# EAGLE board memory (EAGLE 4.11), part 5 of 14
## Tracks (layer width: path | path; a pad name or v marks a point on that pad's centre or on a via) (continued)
-MB08  (via drill 0.61) (continued)
  Bottom 0.254: F11.R2 370.2,26.03 374.65,26.03 375.92,27.3 378.46,27.3 379.1,26.67 387.99,26.67 391.8,30.48 394.33,30.48 397.51,27.3 403.86,27.3 404.5,26.67 413.38,26.67 414.02,27.3 416.56,27.3 417.19,26.67 421.64,26.67 423.55,24.77 423.55,22.86 F07.S2 | v11.43,186.06 13.97,186.06 13.97,181.61 D39.J2 | v13.34,201.29 26.04,214 67.31,214 68.58,212.72 74.93,212.72 75.56,213.36 130.18,213.36 131.44,212.09 134.62,215.26 147.96,215.26 149.22,216.53 160.02,216.53 160.66,215.9 161.93,215.9 v163.19,217.17 | v165.1,240.66 165.74,240.03 171.45,240.03 v172.72,241.3 | v175.9,244.47 176.53,243.84 177.8,243.84 178.44,243.2 182.25,243.2 185.42,246.38 187.96,246.38 188.59,245.75 197.49,245.75 198.12,246.38 200.66,246.38 201.29,245.75 206.38,245.75 207.65,247.01 C24.K2 208.28,248.28 212.09,248.28 213.36,249.56 218.44,249.56 221.62,252.73 224.16,252.73 224.79,252.09 231.14,252.09 v231.78,251.46 | v287.65,283.85 286.38,282.58 269.24,282.58 v268.61,283.21 | v267.97,274.96 255.91,274.96 255.27,274.32 253.37,274.32 250.82,276.86 237.49,276.86 235.59,274.96 v233.04,274.96 | v19.05,412.75 135.89,412.75 137.79,414.66 v144.15,414.66 | v147.96,410.85 149.22,412.12 155.57,412.12 156.84,413.39 189.23,413.39 190.5,412.12 196.22,412.12 198.12,414.02 249.56,414.02 250.82,412.75 267.33,412.75 267.97,412.12 285.12,412.12 v285.75,411.48 | v276.23,365.76 276.23,363.22 286.38,363.22 287.02,363.86 288.29,363.86 289.56,362.59 292.1,362.59 292.74,363.22 294.64,363.22 v295.27,362.59 | v361.95,27.94 360.68,26.67 351.79,26.67 351.15,27.3 342.26,27.3 341.63,26.67 339.09,26.67 338.45,27.3 329.56,27.3 328.93,26.67 326.39,26.67 320.04,33.02 314.96,33.02 313.69,34.29 311.15,34.29 310.51,33.66 306.7,33.66 v303.53,36.83
  Bottom 0.254: v291.46,50.8 290.83,50.16 288.93,50.16 287.65,48.9 278.76,48.9 278.13,49.53 275.59,49.53 274.95,48.9 266.06,48.9 265.43,49.53 262.89,49.53 262.25,48.9 253.37,48.9 252.73,49.53 250.19,49.53 249.56,48.9 247.01,48.9 v242.57,53.34 | v239.4,81.28 238.76,80.64 185.42,80.64 v179.71,86.36 | v180.97,200.66 180.34,201.29 173.99,201.29 173.35,201.93 v167,201.93
-MB09  (via drill 0.61)
  Top 0.254: v15.88,13.97 15.88,42.55 14.61,43.82 F39.J2 | v260.35,5.08 275.59,5.08 276.86,3.81 278.13,3.81 v278.13,11.43 | v204.47,201.93 204.47,212.72 206.38,214.63 206.38,239.39 207.65,240.66 C24.M2 | v165.1,168.28 165.1,156.21 156.84,147.95 156.84,139.06 155.57,137.79 155.57,16.51 147.32,8.25 147.32,4.44 146.05,3.17 144.15,3.17 v142.24,5.08
  Route2 0.254: v142.24,5.08 144.78,2.54 220.34,2.54 222.25,0.63 255.91,0.63 v260.35,5.08 | v278.13,11.43 280.04,9.52 316.23,9.52 317.5,8.25 341.63,8.25 343.54,10.16 352.43,10.16 359.41,17.14 363.86,17.14 365.12,18.41 369.57,18.41 F11.T2 | v204.47,201.93 203.84,201.29 200.03,201.29 196.85,204.47 192.41,204.47 189.23,201.29 186.69,201.29 186.06,201.93 179.71,201.93 176.53,205.1 175.9,205.1 174.62,203.84 173.99,203.84 173.35,204.47 168.28,204.47 v163.83,200.03
  Route3 0.254: v163.83,200.03 161.93,198.12 161.93,191.13 160.66,189.86 165.1,185.42 v165.1,168.28
  Bottom 0.254: v15.88,13.97 23.5,6.35 137.16,6.35 138.43,5.08 v142.24,5.08
-MB10  (via drill 0.61)
  Top 0.254: v28.57,9.52 28.57,38.73 27.94,39.37 27.94,43.18 27.3,43.82 F38.J2 | v226.69,9.52 v226.69,4.44 | v344.81,6.35 346.07,7.62 346.07,29.84 347.35,31.12 347.35,33.02 344.81,35.56 344.81,37.46 F13.L2 | v201.29,231.78 200.03,230.5 200.03,211.45 198.12,209.55 v198.12,201.93 | v191.13,201.29 190.5,200.66 190.5,175.89 v189.23,174.62 | v182.25,82.55 180.34,80.64 180.34,64.77 180.97,64.13 180.97,17.78 177.8,14.61 177.8,8.89 v179.07,7.62
  Route2 0.254: v345.44,85.72 346.71,86.99 351.15,86.99 354.96,90.8 363.86,90.8 364.49,90.17 373.38,90.17 382.9,99.69 389.25,99.69 389.89,100.33 400.05,100.33 400.05,120.02 395.61,124.46 395.61,126.36 E09.D2 | v201.29,231.78 202.56,231.78 203.84,233.04 206.38,233.04 207.65,234.31 C24.P2 | v198.12,201.93 197.49,201.29 v191.13,201.29
  Route3 0.254: v345.44,85.72 346.71,84.45 346.71,69.85 349.25,67.31 349.25,52.7 342.9,46.36 342.9,40.01 344.17,38.73 F13.L2 | v189.23,174.62 188.59,173.99 188.59,173.35 184.15,168.91 184.15,84.45 v182.25,82.55
  Bottom 0.254: v28.57,9.52 29.84,8.25 135.25,8.25 136.53,9.52 138.43,9.52 139.7,8.25 179.07,8.25 | 179.07,8.25 219.07,8.25 220.34,9.52 v226.69,9.52 | v226.69,4.44 227.33,3.81 274.32,3.81 277.5,6.98 302.89,6.98 304.8,5.08 314.96,5.08 316.23,6.35 342.26,6.35 342.9,6.98 344.17,6.98 v344.81,6.35 | v179.07,7.62 179.07,8.25
-MB11  (via drill 0.61)
  Top 0.254: v349.25,51.44 349.25,70.48 350.52,71.75 v350.52,78.1 | v426.72,78.74 431.8,78.74 431.8,106.04 433.07,107.31 E06.L2 | v38.1,69.85 38.1,46.36 39.37,45.09 F37.J2 | v146.05,140.97 v146.05,71.75 | v248.92,140.97 250.82,142.88 250.82,151.76 | 250.82,151.76 v250.82,170.18 | v214,225.42 215.9,223.52 v215.9,208.91 | v238.12,207.64 240.66,207.64 240.66,204.47 241.3,203.84 241.3,186.06 v242.57,184.78 | v322.58,95.25 321.31,96.52 321.31,97.16 320.68,97.79 v320.68,100.96 | v253.37,113.03 254,113.66 254,119.38 252.73,120.65 252.73,121.92 254,123.19 254,139.7 252.73,140.97 252.73,147.95 253.37,148.59 253.37,149.22 250.82,151.76
  Route2 0.254: v349.25,51.44 344.81,51.44 F13.F2
  Route3 0.254: v350.52,78.1 350.52,80.64 349.25,81.91 349.25,86.99 v341,95.25
  Bottom 0.254: v350.52,78.1 365.76,78.1 367.67,80.01 407.04,80.01 408.31,78.74 v426.72,78.74 | E06.E2 436.88,123.19 436.88,118.74 437.51,118.74 444.5,111.76 444.5,109.22 440.69,109.22 440.06,109.85 438.15,109.85 436.25,107.95 433.7,107.95 E06.L2 | v38.1,69.85 40.01,71.75 v146.05,71.75 | v146.05,140.97 146.69,140.34 248.28,140.34 v248.92,140.97 | 250.82,172.72 250.82,174.62 255.27,174.62 D20.L2 | v250.82,170.18 250.82,172.72 | v214,225.42 212.09,227.33 208.91,227.33 208.28,227.97 C24.S2 | v215.9,208.91 217.17,207.64 229.24,207.64 229.87,207.01 237.49,207.01 v238.12,207.64 | v242.57,184.78 240.03,182.25 237.49,182.25 236.85,182.88 236.22,182.88 231.78,178.44 231.78,176.53 234.95,176.53 235.59,177.16 238.12,177.16 239.4,175.89 245.75,175.89 248.92,172.72 250.82,172.72 | v341,95.25 339.09,93.34 329.56,93.34 328.93,93.98 326.39,93.98 325.75,93.34 324.49,93.34 v322.58,95.25 | v320.68,100.96 320.68,102.87 314.96,102.87 311.15,106.68 300.99,106.68 300.36,106.04 291.46,106.04 287.65,109.85 285.12,109.85 281.94,106.68 278.13,106.68 274.95,109.85 266.06,109.85 265.43,109.22 262.89,109.22 262.25,109.85 256.54,109.85 v253.37,113.03
-MBSH  (via drill 0.61)
  Top 0.254: D16.U2 309.25,153.03 307.98,154.31 307.98,165.73 306.7,167 306.7,167.64 D16.N2 | F05.K2 448.94,41.91 447.68,43.18 447.68,55.25 446.4,56.52 F05.D2 | v433.7,116.2 431.8,118.11 431.8,125.09 433.07,126.36 E06.D2 433.07,127.63 431.8,128.91 431.8,142.24 v429.89,144.14 | 371.48,170.18 370.2,168.91 D11.N2 | 371.48,175.89 371.48,170.18 | 371.48,175.89 372.75,177.16 D11.K2 | 371.48,170.18 371.48,154.31 372.75,153.03 D11.U2 373.38,151.76 v373.38,143.51 | 371.48,175.89 371.48,191.77 370.2,193.04 D11.D2 | v443.23,57.15 441.32,59.05 441.32,109.22 v439.42,111.12
  Route2 0.254: v443.23,57.15 445.77,57.15 F05.D2
  Bottom 0.254: D16.N2 306.7,168.91 307.98,170.18 314.96,170.18 316.23,168.91 318.77,168.91 D15.N2 319.4,168.91 320.68,170.18 325.75,170.18 327.02,168.91 331.47,168.91 D14.N2 332.11,168.91 334.01,168.91 335.28,170.18 338.45,170.18 339.73,168.91 344.17,168.91 D13.N2 344.81,167.64 346.07,166.37 353.06,166.37 354.33,167.64 356.87,167.64 D12.N2 357.5,168.91 358.77,170.18 365.76,170.18 367.03,168.91 369.57,168.91 D11.N2 | D16.U2 309.88,151.76 312.42,151.76 313.69,150.5 320.68,150.5 321.94,151.76 D15.U2 322.58,153.03 326.39,153.03 327.66,154.31 328.93,154.31 330.2,153.03 334.64,153.03 D14.U2 335.28,153.03 339.73,153.03 341,154.31 341.63,154.31 342.26,153.67 346.71,153.67 347.35,153.03 D13.U2 347.98,153.03 350.52,153.03 351.79,154.31 354.33,154.31 356.24,152.4 360.05,152.4 D12.U2 | D16.D2 306.7,194.31 307.98,195.58 313.69,195.58 315.6,193.67 318.77,193.67 D15.D2 319.4,194.31 320.68,195.58 326.39,195.58 328.3,193.67 331.47,193.67 D14.D2 332.11,194.31 333.38,195.58 339.09,195.58 341,193.67 344.17,193.67 D13.D2 344.81,194.31 346.07,195.58 351.79,195.58 353.69,193.67 356.87,193.67 D12.D2 357.5,194.31 358.77,195.58 364.49,195.58 366.39,193.67 369.57,193.67 D11.D2 | D16.K2 309.88,178.44 314.32,178.44 315.6,179.7 316.87,179.7 318.13,178.44 321.94,178.44 D15.K2 322.58,178.44 327.02,178.44 328.3,179.7 329.56,179.7 330.83,178.44 334.64,178.44 D14.K2 335.28,178.44 339.73,178.44 341,179.7 346.07,179.7 347.35,178.44 D13.K2 347.98,177.8 351.79,177.8 353.69,179.7 354.96,179.7 356.24,178.44 360.05,178.44 D12.K2 360.68,177.8 364.49,177.8 366.39,175.89 371.48,175.89 372.75,177.16 D11.K2 373.38,177.16 375.92,177.16 377.19,175.89 385.44,175.89 385.44,172.09 D10.M2
  Bottom 0.254: v433.7,116.2 436.25,116.2 436.25,111.76 E06.K2 436.88,111.12 v439.42,111.12 | v429.89,144.14 412.75,144.14 412.12,143.51 398.14,143.51 396.88,142.24 382.27,142.24 381,143.51 v373.38,143.51
-MCA  (via drill 0.61)
  Top 0.254: v80.01,147.95 79.38,148.59 v79.38,214.63 | v131.44,213.36 132.08,214 132.08,220.34 133.35,221.61 133.35,233.04 135.25,234.95 v135.25,235.59 | C29.H2 144.78,253.36 144.78,249.56 146.05,248.28 146.05,236.85 144.78,235.59 C29.P2
  Route3 0.254: v14.61,152.4 14.61,154.94 D39.T2
  Bottom 0.254: v14.61,152.4 19.68,147.32 35.56,147.32 39.37,151.13 48.26,151.13 48.9,150.5 55.24,150.5 58.42,147.32 77.47,147.32 78.11,147.95 v80.01,147.95 | v79.38,214.63 80.01,214 130.81,214 v131.44,213.36 | v135.25,235.59 136.53,236.85 142.88,236.85 144.15,235.59 C29.P2
-MCB  (via drill 0.61)
  Top 0.254: v139.7,228.6 139.7,250.19 132.08,257.81 132.08,259.72 C30.E2
  Route2 0.254: v139.7,228.6 144.15,228.6 C29.S2
-MCC
  Top 0.254: C30.P2 132.08,235.59 132.72,236.22 132.72,240.03 133.35,240.66 133.35,252.09 132.08,253.36 C30.H2
-MCD  (via drill 0.61)
  Top 0.254: v128.91,259.08 136.53,251.46 136.53,243.84 135.25,242.57 135.25,241.3 133.35,239.39 133.35,234.31 132.72,233.68 132.72,229.87 132.08,229.23 C30.S2
  Bottom 0.254: v128.91,259.08 128.27,258.44 124.46,258.44 123.19,259.72 119.38,259.72 C31.E2
-MCE
  Top 0.254: C31.P2 119.38,235.59 119.38,239.39 120.65,240.66 120.65,252.09 119.38,253.36 C31.H2
-MCF  (via drill 0.61)
  Top 0.254: 107.95,227.33 107.95,254.63 106.68,255.91 106.68,259.72 C32.E2 | 107.95,227.33 107.95,196.22 107.31,195.58 107.31,191.77 106.68,191.13 D32.E2 | 107.95,227.33 v109.86,227.33
  Bottom 0.254: v109.86,227.33 110.49,226.69 117.47,226.69 118.75,227.97 C31.S2
-MCG
  Route3 0.254: C32.P2 106.05,235.59 104.78,236.85 104.78,248.92 106.05,250.19 106.05,253.36 C32.H2
-MCH  (via drill 0.61)
  Top 0.254: v24.13,155.57 24.77,156.21 24.77,157.48 25.4,158.11 v25.4,206.38 | v98.42,207.64 98.42,222.88 v99.69,224.16 | v114.3,229.87 v114.3,261.62
  Bottom 0.254: v24.13,155.57 22.23,153.67 18.41,153.67 17.78,153.03 D39.U2 | v25.4,206.38 26.67,207.64 31.75,207.64 32.38,207.01 68.58,207.01 69.85,208.28 73.03,208.28 74.3,207.01 97.79,207.01 v98.42,207.64 | v99.69,224.16 103.5,227.97 106.05,227.97 C32.S2 106.68,229.23 111.12,229.23 112.39,230.5 113.67,230.5 v114.3,229.87 | v114.3,261.62 122.56,261.62 123.19,262.25 125.73,262.25 126.36,261.62 135.25,261.62 135.89,262.25 142.88,262.25 144.15,260.99 C29.E2
-MEM00  (via drill 0.61)
  Top 0.254: v142.24,45.72 146.05,45.72 146.05,70.48 v147.32,71.75 | F22.D2 230.5,57.79 230.5,58.42 231.78,59.69 v231.78,72.39 230.5,73.66 230.5,80.01 228.6,81.91 228.6,90.17 v229.87,91.44 | 238.76,238.12 238.12,238.76 v238.12,253.36 | 238.76,238.12 v240.03,236.85 | v236.22,234.95 238.76,237.49 238.76,238.12
  Route2 0.254: v367.03,217.81 364.49,217.81 363.22,216.53 317.5,216.53 309.88,224.16 304.17,224.16 v297.18,231.14 | v238.12,253.36 233.04,258.44 226.69,258.44 222.25,262.89 217.81,262.89 C23.D2
  Route3 0.254: v367.03,217.81 368.3,216.53 368.3,189.23 369.57,187.96 D11.F2 | v240.03,101.6 238.12,103.5 238.12,116.84 234.95,120.02 234.95,132.08 v233.04,133.99 | v230.5,135.25 227.97,137.79 227.97,151.13 228.6,151.76 228.6,211.45 234.31,217.17 234.31,220.98 234.95,221.61 234.95,233.68 v236.22,234.95
  Bottom 0.254: v142.24,45.72 137.79,45.72 137.16,46.36 132.08,46.36 132.08,41.91 F30.K2 | v147.32,71.75 147.96,72.39 189.87,72.39 190.5,71.75 191.77,71.75 192.41,72.39 210.19,72.39 210.82,73.02 231.14,73.02 v231.78,72.39 | v297.18,231.14 295.27,233.04 288.29,233.04 287.65,233.68 278.76,233.68 278.13,233.04 275.59,233.04 274.95,233.68 268.61,233.68 267.97,233.04 262.89,233.04 262.25,233.68 253.37,233.68 252.73,233.04 252.09,233.04 248.28,236.85 v240.03,236.85 | v229.87,91.44 v240.03,101.6 | v233.04,133.99 231.78,135.25 v230.5,135.25
-MEM01  (via drill 0.61)
  Top 0.254: v130.18,43.18 130.18,36.83 131.44,35.56 F30.M2
  Route2 0.254: D11.R2 370.2,161.29 370.2,159.38 371.48,158.11 371.48,145.41 361.95,145.41 357.5,140.97 321.94,140.97 320.68,142.24 299.72,142.24 298.45,140.97 255.27,140.97 252.73,138.43 251.46,138.43 v249.56,136.53 248.28,135.25 243.21,135.25 238.12,140.34 221.62,140.34 v217.81,144.14
  Route3 0.254: v249.56,136.53 247.65,134.62 247.65,81.91 250.82,78.74 250.82,66.04 255.27,61.59 v255.27,59.05 | v217.81,144.14 212.72,149.22 212.72,200.66 211.46,201.93 211.46,213.36 212.72,214.63 212.72,256.54 217.17,256.54 C23.F2
  Bottom 0.254: v130.18,43.18 130.18,48.9 137.16,48.9 137.79,49.53 139.06,49.53 139.7,48.9 149.86,48.9 150.5,49.53 159.38,49.53 160.02,48.9 162.56,48.9 163.19,49.53 172.09,49.53 172.72,48.9 175.26,48.9 175.9,49.53 184.78,49.53 185.42,48.9 187.96,48.9 188.59,49.53 197.49,49.53 198.12,48.9 200.66,48.9 201.29,49.53 207.65,49.53 210.82,52.7 213.36,52.7 214,52.07 222.88,52.07 226.69,55.88 231.78,55.88 233.04,54.61 F22.E2 233.68,54.61 236.22,54.61 237.49,55.88 240.03,55.88 240.66,55.25 251.46,55.25 v255.27,59.05
-MEM02  (via drill 0.61)
  Top 0.254: v136.53,8.25 136.53,27.94 132.08,27.94 F30.P2 | v229.24,10.79 228.6,11.43 228.6,48.9 229.87,50.16 F22.F2 | v356.87,207.64 358.77,205.74 358.77,189.23 357.5,187.96 D12.F2 | v338.45,212.72 v338.45,207.64 | v242.57,208.91 239.4,212.09 v239.4,219.07 | v229.24,224.16 228.6,224.79 228.6,243.2 v224.16,247.65
  Route2 0.254: v356.87,207.64 355.6,208.91 349.88,208.91 347.98,207.01 339.09,207.01 v338.45,207.64 | v338.45,212.72 336.55,210.82 277.5,210.82 272.42,205.74 245.75,205.74 v242.57,208.91 | v239.4,219.07 237.49,220.98 232.41,220.98 v229.24,224.16 | v224.16,247.65 221.62,250.19 217.81,250.19 C23.J2
  Route3 0.254: v239.4,219.07 239.4,215.26 231.78,207.64 231.78,81.91 230.5,80.64 230.5,72.39 231.78,71.12 231.78,62.87 231.14,62.23 231.14,59.05 231.78,58.42 231.78,52.7 230.5,51.44 F22.F2
  Bottom 0.254: v136.53,8.25 138.43,6.35 160.66,6.35 161.29,5.71 178.44,5.71 179.71,6.98 204.47,6.98 205.1,7.62 219.71,7.62 220.34,8.25 226.69,8.25 v229.24,10.79
-MEM03  (via drill 0.61)
  Top 0.254: v194.94,13.34 206.38,24.77 206.38,34.29 203.2,37.46 v203.2,40.64 | v264.8,161.92 263.52,163.19 263.52,189.86 262.25,191.13 v262.25,191.77
  Route2 0.254: v194.94,13.34 194.31,13.97 188.59,13.97 184.78,17.78 175.9,17.78 175.26,17.14 166.37,17.14 162.56,20.95 153.67,20.95 149.86,17.14 140.97,17.14 137.16,20.95 132.72,20.95 132.08,21.59 F30.S2 | v335.28,167.64 v332.11,170.81 | v313.69,175.89 307.34,182.25 301.62,182.25 v294,189.86 | v248.92,241.3 247.01,243.2 237.49,243.2 236.85,242.57 227.97,242.57 227.33,243.2 224.79,243.2 224.16,242.57 222.88,242.57 221.62,243.84 217.81,243.84 C23.L2 | v242.57,90.8 v233.68,81.91
  Route3 0.254: v252.73,192.41 252.09,193.04 252.09,194.94 250.82,196.22 250.82,238.76 248.92,240.66 v248.92,241.3 | v233.68,81.91 233.68,78.1 238.12,73.66 238.12,48.26 233.68,48.26 F22.H2 | v261.62,98.42 263.52,100.33 263.52,113.03 266.7,116.2 266.7,160.02 v264.8,161.92
  Bottom 0.254: v203.2,40.64 208.91,46.36 213.36,46.36 214,45.72 222.88,45.72 223.52,46.36 226.06,46.36 226.69,45.72 231.78,45.72 233.04,46.99 F22.H2 | v335.28,167.64 342.26,160.66 345.44,160.66 348.62,163.83 351.15,163.83 353.06,161.92 356.87,161.92 D12.R2 | v332.11,170.81 326.39,176.53 316.87,176.53 316.23,175.89 v313.69,175.89 | v294,189.86 291.46,192.41 288.29,192.41 287.65,191.77 278.76,191.77 278.13,192.41 275.59,192.41 274.95,191.77 266.06,191.77 265.43,192.41 262.89,192.41 v262.25,191.77 253.37,191.77 v252.73,192.41 | v242.57,90.8 245.11,93.34 250.19,93.34 253.37,96.52 259.71,96.52 v261.62,98.42
-MEM04  (via drill 0.61)
  Top 0.254: v127,13.34 127,17.14 128.27,18.41 F30.T2 | v215.9,10.16 212.72,13.34 212.72,24.77 215.9,27.94 v215.9,41.27 | v328.93,182.25 327.02,182.25 327.02,203.2 325.75,204.47 v325.75,208.28 | v252.73,208.91 252.09,209.55 v252.09,218.44 | v240.03,224.16 238.12,226.06 v238.12,231.78 | v211.46,65.41 211.46,80.64 212.72,81.91 v212.72,92.71 | v216.53,115.57 218.44,117.47 218.44,119.38 219.07,120.02 219.07,147.32 220.34,148.59 v220.34,149.86
  Route2 0.254: v341.63,186.06 343.54,186.06 344.17,186.69 D13.F2
  Route3 0.254: v238.12,231.78 238.12,233.04 237.49,233.68 237.49,234.95 236.22,236.22 231.78,236.22 | 231.78,236.22 229.87,236.22 v229.87,234.95 | v215.9,41.27 215.9,50.16 212.72,53.34 212.72,64.13 v211.46,65.41 | v212.72,92.71 215.9,95.88 215.9,114.93 v216.53,115.57 | v220.34,149.86 222.25,151.76 222.25,201.29 222.88,201.93 222.88,209.55 226.06,212.72 226.06,219.07 228.6,221.61 228.6,223.52 227.97,224.16 227.97,225.42 231.78,229.23 231.78,236.22
  Bottom 0.254: v127,13.34 127,10.79 138.43,10.79 140.34,8.89 202.56,8.89 203.2,9.52 215.26,9.52 v215.9,10.16 | v215.9,41.27 217.17,42.55 226.06,42.55 227.33,43.82 229.87,43.82 F22.J2 | v341.63,186.06 339.09,186.06 335.28,182.25 v328.93,182.25 | v325.75,208.28 325.12,208.91 313.06,208.91 311.79,207.64 296.55,207.64 295.91,207.01 290.83,207.01 290.19,207.64 254,207.64 v252.73,208.91 | v252.09,218.44 246.38,224.16 v240.03,224.16 | v229.87,234.95 227.97,233.04 224.79,233.04 224.16,233.68 219.71,233.68 218.44,234.95 218.44,237.49 217.81,237.49 C23.N2
-MEM05  (via drill 0.61)
  Top 0.254: v234.95,13.97 234.95,39.37 233.68,40.64 F22.K2 | v217.81,228.6 217.81,231.14 C23.R2 | v223.52,227.33 225.43,227.33 225.43,212.09 224.16,210.82 v224.16,203.2 | v316.87,185.42 314.32,187.96 314.32,205.1 309.25,210.19 v309.25,219.71
  Route2 0.254: v217.81,228.6 219.07,227.33 v223.52,227.33 | v335.28,168.91 340.36,173.99 341,173.99 342.9,175.89 342.9,179.7 339.09,179.7 338.45,179.07 335.28,179.07 333.38,180.97 333.38,184.78 v334.64,186.06
  Route3 0.254: v224.16,203.2 225.43,201.93 225.43,127.63 228.6,124.46 228.6,69.22 229.87,67.94 229.87,66.67 228.6,65.41 228.6,48.26 233.04,43.82 233.04,41.91 F22.K2
  Bottom 0.254: v234.95,13.97 228.6,13.97 225.43,10.79 223.52,10.79 222.88,11.43 215.9,11.43 214.63,10.16 202.56,10.16 201.93,9.52 140.97,9.52 135.89,14.61 134.62,14.61 133.99,13.97 129.54,13.97 128.91,13.34 F30.V2 | v335.28,168.91 341,163.19 343.54,163.19 344.17,162.56 D13.R2 | v334.64,186.06 326.39,186.06 325.75,185.42 v316.87,185.42 | v309.25,219.71 308.61,220.34 300.99,220.34 300.36,220.98 291.46,220.98 290.83,220.34 290.19,220.34 283.85,226.69 276.86,226.69 274.95,228.6 273.69,228.6 271.78,226.69 262.89,226.69 262.25,227.33 253.37,227.33 252.73,226.69 250.19,226.69 249.56,227.33 240.66,227.33 240.03,226.69 237.49,226.69 236.85,227.33 227.97,227.33 227.33,226.69 224.79,226.69 224.16,227.33 v223.52,227.33
-MEM06  (via drill 0.61)
  Top 0.254: v179.07,274.32 177.8,273.05 177.8,265.43 179.07,264.16 C26.D2 | v228.6,254 228.6,256.54 225.43,259.72 v225.43,260.99
  Route2 0.254: v106.68,76.2 107.95,74.93 111.12,74.93 118.11,67.94 121.28,67.94 124.46,64.77 125.73,64.77 128.27,67.31 128.91,67.31 143.51,52.7 149.86,52.7 153.67,48.9 162.56,48.9 163.19,49.53 172.09,49.53 179.07,42.55 187.96,42.55 188.59,43.18 197.49,43.18 201.29,39.37 v205.74,39.37 | v179.07,274.32 177.8,275.59 165.74,275.59 165.1,276.23 140.97,276.23 139.7,274.96 137.79,274.96 v116.84,254 | v303.53,193.67 305.44,191.77 313.06,191.77 313.69,192.41 322.58,192.41 326.39,188.59 330.83,188.59 331.47,187.96 D14.F2
  Route3 0.254: 101.6,125.09 102.87,126.36 E32.D2 | 101.6,125.09 101.6,81.28 v106.68,76.2 | v116.84,254 117.47,253.36 117.47,203.84 111.12,197.48 111.12,153.03 101.6,143.51 101.6,125.09 | v303.53,193.67 301.62,195.58 301.62,226.69 298.45,229.87 298.45,243.2 v296.55,245.11 | v274.95,246.38 274.32,247.01 v274.32,248.92
  Bottom 0.254: v205.74,39.37 206.38,40.01 213.36,40.01 214,39.37 214.63,39.37 215.26,40.01 226.06,40.01 227.33,38.73 229.87,38.73 F22.L2 | v296.55,245.11 295.91,245.75 288.29,245.75 287.65,246.38 278.76,246.38 278.13,245.75 275.59,245.75 v274.95,246.38 | v274.32,248.92 271.14,252.09 262.89,252.09 262.25,252.73 253.37,252.73 252.73,252.09 250.19,252.09 249.56,252.73 240.66,252.73 240.03,252.09 237.49,252.09 236.85,252.73 229.87,252.73 v228.6,254 | v225.43,260.99 224.79,261.62 215.26,261.62 214.63,262.25 212.09,262.25 211.46,261.62 208.91,261.62 205.74,264.8 203.2,264.8 201.93,263.53 200.66,263.53 198.75,261.62 189.87,261.62 189.23,262.25 187.96,262.25 185.42,259.72 184.15,259.72 183.51,259.08 181.61,259.08 179.71,260.99 179.71,262.89 C26.D2
-MEM07  (via drill 0.61)
  Top 0.254: v150.5,179.7 152.4,181.61 152.4,238.76 154.31,240.66 v154.31,242.57
  Route2 0.254: v154.31,242.57 163.83,252.09 172.09,252.09 176.53,256.54 179.07,256.54 C26.F2 | E32.E2 106.68,124.46 106.68,128.91 109.22,128.91 118.75,138.43 v140.97,138.43 140.97,142.24 173.35,142.24 v188.59,127 | v182.25,127 195.58,113.66 196.85,113.66 214,96.52 222.88,96.52 223.52,97.16 224.16,97.16 227.97,93.34 234.95,93.34 v236.22,92.07
  Route3 0.254: v140.97,138.43 144.78,138.43 144.78,150.5 149.22,154.94 149.22,178.44 v150.5,179.7 | 234.95,92.07 234.95,95.88 236.22,97.16 v236.85,97.16 | 234.95,92.07 234.95,78.1 241.3,71.75 241.3,46.99 234.95,40.64 234.95,36.83 233.68,35.56 F22.M2 | v303.53,102.87 304.8,104.14 304.8,115.57 311.15,121.92 311.15,156.84 v314.32,160.02 | 234.95,92.07 v236.22,92.07
  Bottom 0.254: v236.85,97.16 237.49,96.52 246.38,96.52 253.37,103.5 260.35,103.5 260.99,104.14 263.52,104.14 264.8,102.87 271.78,102.87 273.05,104.14 276.23,104.14 277.5,102.87 284.48,102.87 285.75,104.14 288.93,104.14 290.19,102.87 297.81,102.87 299.08,104.14 301.62,104.14 302.89,102.87 v303.53,102.87 | v314.32,160.02 315.6,161.29 317.5,161.29 318.13,160.66 321.94,160.66 325.12,163.83 327.66,163.83 328.93,162.56 331.47,162.56 D14.R2 | v188.59,127 186.69,125.09 184.78,125.09 182.88,127 v182.25,127
-MEM08  (via drill 0.61)
  Top 0.254: v229.87,34.29 229.87,32.38 F22.N2 | v141.6,53.34 139.7,55.25 139.7,112.39 v137.79,114.3 | v187.32,235.59 187.32,220.98 189.23,219.07 v189.23,205.74 189.23,205.1 193.68,200.66 193.68,118.11 v191.77,116.2 | v317.5,198.75 317.5,189.23 318.77,187.96 D15.F2
  Route2 0.254: v229.87,34.29 224.16,40.01 215.26,40.01 211.46,36.2 202.56,36.2 201.93,36.83 199.39,36.83 198.75,36.2 189.87,36.2 186.06,40.01 177.16,40.01 173.35,36.2 164.47,36.2 154.94,45.72 149.22,45.72 v141.6,53.34 | v317.5,198.75 311.15,205.1 v278.13,205.1 | v239.4,206.38 238.12,205.1 213.36,205.1 211.46,207.01 190.5,207.01 v189.23,205.74
  Route3 0.254: v187.32,235.59 187.32,238.76 180.97,245.11 180.97,248.92 179.71,250.19 C26.J2
  Bottom 0.254: E32.H2 106.68,116.84 109.22,116.84 110.49,115.57 121.28,115.57 125.09,119.38 132.72,119.38 v137.79,114.3 139.7,116.2 147.96,116.2 148.59,115.57 157.48,115.57 161.29,119.38 170.18,119.38 177.16,112.39 187.96,112.39 v191.77,116.2 | v278.13,205.1 276.86,206.38 v239.4,206.38
-MEM09  (via drill 0.61)
  Top 0.254: 177.8,99.06 v175.9,100.96 | v177.8,35.56 177.8,99.06 | v233.04,33.02 233.04,29.21 F22.P2 | v175.9,192.41 177.8,194.31 177.8,242.57 179.07,243.84 C26.L2 | v175.9,174.62 177.8,172.72 v177.8,153.67 177.8,99.06
  Route2 0.254: v294,153.03 v299.72,158.75
  Route3 0.254: v106.68,107.95 106.68,110.49 E32.K2 | v175.9,192.41 174.62,191.13 174.62,175.89 v175.9,174.62
  Bottom 0.254: v106.68,107.95 111.76,102.87 121.28,102.87 121.92,103.5 124.46,103.5 125.09,102.87 133.99,102.87 134.62,103.5 137.16,103.5 137.79,102.87 146.69,102.87 147.32,103.5 149.86,103.5 150.5,102.87 159.38,102.87 160.02,103.5 162.56,103.5 163.19,102.87 172.09,102.87 172.72,103.5 173.35,103.5 v175.9,100.96 | v177.8,35.56 178.44,36.2 184.15,36.2 184.78,35.56 187.32,35.56 188.59,36.83 197.49,36.83 198.12,36.2 200.66,36.2 201.29,36.83 203.84,36.83 207.01,33.66 213.36,33.66 214,33.02 222.25,33.02 224.16,34.92 224.79,34.92 226.69,33.02 v233.04,33.02 | v299.72,158.75 300.36,158.75 302.26,160.66 303.53,160.66 304.17,160.02 313.06,160.02 314.96,161.92 318.77,161.92 D15.R2 | v294,153.03 291.46,150.5 288.29,150.5 287.65,151.13 286.38,151.13 283.21,147.95 278.13,147.95 274.95,151.13 266.06,151.13 265.43,150.5 262.89,150.5 262.25,151.13 253.37,151.13 252.73,150.5 251.46,150.5 248.92,153.03 247.65,153.03 246.38,154.31 237.49,154.31 236.85,153.67 235.59,153.67 233.68,155.57 232.41,155.57 231.14,154.31 224.79,154.31 224.16,153.67 215.26,153.67 214.63,154.31 212.09,154.31 211.46,153.67 202.56,153.67 201.93,154.31 199.39,154.31 198.75,153.67 189.87,153.67 189.23,154.31 186.69,154.31 186.06,153.67 v177.8,153.67
-MEM10  (via drill 0.61)
  Top 0.254: v135.25,210.82 135.25,202.56 133.35,200.66 133.35,175.26 130.18,172.09 130.18,130.81 v128.27,128.91 | v302.89,180.97 304.8,182.88 304.8,185.42 306.07,186.69 D16.F2 | v288.29,190.5 288.93,191.13 v288.93,203.2
  Route2 0.254: v120.65,92.71 109.86,103.5 107.31,103.5 106.68,104.14 E32.M2 106.68,105.41 107.95,105.41 107.95,108.58 v128.27,128.91 | v172.72,211.45 171.45,210.19 138.43,210.19 137.79,210.82 v135.25,210.82 | v302.89,180.97 300.99,179.07 299.72,179.07 v288.29,190.5 | v241.94,207.64 238.12,211.45 233.68,211.45 231.78,209.55 229.87,209.55 228.6,208.28 217.81,208.28 215.9,206.38 214.63,206.38 212.09,208.91 200.03,208.91 v198.12,210.82
  Route3 0.254: v176.53,81.28 177.8,80.01 177.8,54.61 v203.84,28.58 | v172.72,211.45 177.8,216.53 177.8,236.22 179.07,237.49 C26.N2
  Bottom 0.254: v120.65,92.71 126.36,86.99 137.16,86.99 137.79,87.63 146.69,87.63 150.5,83.82 159.38,83.82 165.74,90.17 167.64,90.17 v176.53,81.28 | v203.84,28.58 205.1,27.3 213.36,27.3 214,26.67 222.88,26.67 223.52,27.3 224.79,27.3 226.06,26.03 229.87,26.03 F22.R2 | v288.93,203.2 287.02,205.1 279.4,205.1 277.5,207.01 251.46,207.01 249.56,208.91 247.01,208.91 245.75,207.64 v241.94,207.64 | v198.12,210.82 197.49,211.45 176.53,211.45 175.9,210.82 173.99,210.82 173.35,211.45 v172.72,211.45
-MEM11  (via drill 0.61)
  Top 0.254: 161.93,100.33 165.1,103.5 v165.1,147.95 | 161.93,100.33 v160.02,98.42 | v190.5,150.5 190.5,172.09 187.32,175.26 187.32,219.71 179.71,227.33 179.71,231.14 C26.R2 | v232.41,19.05 232.41,20.95 233.04,21.59 F22.S2 | v175.9,19.05 168.28,26.67 168.28,85.09 161.93,91.44 161.93,100.33
  Route2 0.254: v299.72,143.51 298.45,142.24 242.57,142.24 241.3,143.51 237.49,143.51 v236.85,142.88 | v201.29,142.88 193.68,150.5 v190.5,150.5
  Route3 0.254: v303.53,161.92 301.62,160.02 301.62,145.41 v299.72,143.51
  Bottom 0.254: v160.02,98.42 158.12,96.52 150.5,96.52 149.86,97.16 147.32,97.16 146.69,96.52 137.79,96.52 137.16,97.16 134.62,97.16 133.99,96.52 125.09,96.52 124.46,97.16 121.92,97.16 121.28,96.52 112.39,96.52 111.76,97.16 107.31,97.16 106.68,97.79 E32.P2 | v165.1,147.95 165.74,147.32 181.61,147.32 185.42,151.13 187.96,151.13 188.59,150.5 v190.5,150.5 | v232.41,19.05 231.14,17.78 224.79,17.78 224.16,17.14 215.26,17.14 214.63,17.78 212.09,17.78 211.46,17.14 202.56,17.14 201.93,17.78 199.39,17.78 198.75,17.14 189.87,17.14 189.23,17.78 186.69,17.78 186.06,17.14 177.8,17.14 v175.9,19.05 | v303.53,161.92 306.07,161.92 D16.R2 | v236.85,142.88 236.22,143.51 222.88,143.51 222.25,142.88 v201.29,142.88
-MEMPB  (via drill 0.61)
  Top 0.254: v180.97,208.28 180.97,219.71 180.34,220.34 180.34,224.16 179.71,224.79 C26.T2 | v214,149.22 214,139.06 215.9,137.16 215.9,125.09 v217.17,123.82 | v229.87,23.49 229.87,19.69 F22.T2 | v403.86,6.98 403.86,2.54 439.42,2.54 450.85,13.97 450.85,33.02 449.58,34.29 F05.M2 | v275.59,3.81 257.18,3.81 v257.18,19.05
  Route2 0.254: v185.42,184.15 200.03,169.54 200.03,154.31 208.91,154.31 v214,149.22 | v403.86,6.98 403.23,6.35 378.46,6.35 377.82,6.98 372.11,6.98 367.03,1.9 290.83,1.9 285.75,6.98 280.04,6.98 276.86,3.81 v275.59,3.81
  Route3 0.254: v180.97,208.28 184.15,205.1 184.15,185.42 v185.42,184.15 | v224.16,123.82 224.16,122.55 225.43,121.28 225.43,92.71 222.25,89.53 222.25,71.75 225.43,68.58 225.43,27.94 v229.87,23.49
  Bottom 0.254: v217.17,123.82 218.44,125.09 222.25,125.09 223.52,123.82 v224.16,123.82 | v257.18,19.05 257.18,20.32 250.19,20.32 249.56,20.95 240.66,20.95 240.03,20.32 237.49,20.32 234.31,23.49 v229.87,23.49
-MPC  (via drill 0.61)
  Top 0.254: 98.42,249.56 102.87,254 102.87,256.54 C32.F2 | 98.42,249.56 v96.52,247.65 | v98.42,232.41 98.42,249.56 | v109.86,40.01 111.12,41.27 111.12,72.39 v113.03,74.29 | v181.61,75.56 187.32,81.28 187.32,92.71 | 187.32,92.71 189.87,95.25 191.77,95.25 E25.R2 | 187.32,120.02 191.77,120.02 E25.F2 | 187.32,92.71 187.32,120.02 | v142.88,149.86 142.88,200.66 140.97,202.56 140.97,210.82 139.7,212.09 139.7,226.06 140.97,227.33 140.97,231.14 C29.R2 | 187.32,120.02 v187.32,146.69
  Bottom 0.254: C29.R2 140.97,232.41 136.53,232.41 135.25,233.68 130.18,233.68 128.91,232.41 C30.R2 128.27,232.41 125.73,232.41 124.46,233.68 117.47,233.68 116.2,232.41 C31.R2 115.57,232.41 113.03,232.41 111.76,233.68 104.78,233.68 103.5,232.41 C32.R2 102.87,232.41 v98.42,232.41 | C29.F2 140.97,257.81 140.34,258.44 135.89,258.44 135.25,259.08 130.18,259.08 128.91,257.81 C30.F2 128.27,257.81 123.83,257.81 122.56,259.08 117.47,259.08 116.2,257.81 C31.F2 115.57,257.81 114.94,258.44 110.49,258.44 109.86,259.08 109.22,259.08 107.95,257.81 103.5,257.81 C32.F2 | v96.52,247.65 94.61,245.75 87,245.75 83.19,249.56 74.3,249.56 70.48,245.75 61.59,245.75 57.78,249.56 48.9,249.56 48.26,248.92 45.72,248.92 45.09,249.56 36.2,249.56 35.56,248.92 24.77,248.92 20.95,252.73 13.97,252.73 10.16,248.92 5.71,248.92 5.08,248.28 C40.K2 | E25.F2 192.41,121.28 196.85,121.28 198.12,122.55 199.39,122.55 201.29,120.65 204.47,120.65 E24.F2 205.1,121.28 206.38,122.55 211.46,122.55 212.72,121.28 217.17,121.28 E23.F2 | E23.R2 217.17,95.88 213.36,95.88 212.09,97.16 206.38,97.16 205.1,95.88 E24.R2 204.47,95.88 203.84,96.52 199.39,96.52 198.75,97.16 193.68,97.16 192.41,95.88 E25.R2 | v109.86,40.01 106.68,40.01 106.68,35.56 F32.M2 | v113.03,74.29 113.67,73.66 144.15,73.66 144.78,74.29 180.34,74.29 v181.61,75.56 | v142.88,149.86 145.41,147.32 158.75,147.32 160.02,146.05 186.69,146.05 v187.32,146.69
-MR  (via drill 0.61)
  Top 0.254: F37.U2 42.55,16.51 38.1,16.51 33.02,21.59 30.48,21.59 F38.S2 | v195.58,31.12 193.68,29.21 193.68,22.86 180.97,10.16 180.97,5.71 177.16,1.9 114.3,1.9 v114.3,12.06
  Route2 0.254: v379.73,57.15 374.01,51.44 374.01,49.53 365.76,49.53 v360.68,44.45 | v356.87,35.56 354.33,33.02 351.79,33.02 351.15,33.66 342.26,33.66 341.63,33.02 339.09,33.02 337.82,34.29 336.55,34.29 335.28,33.02 326.39,33.02 325.75,33.66 321.31,33.66 320.68,33.02 313.69,33.02 313.06,33.66 304.17,33.66 303.53,33.02 300.99,33.02 297.18,36.83 288.29,36.83 284.48,33.02 275.59,33.02 274.95,33.66 272.42,33.66 269.24,30.48 262.89,30.48 262.25,29.84 253.37,29.84 249.56,33.66 240.66,33.66 240.03,33.02 237.49,33.02 236.85,33.66 235.59,33.66 233.68,31.75 232.41,31.75 231.14,33.02 226.06,33.02 224.16,34.92 222.25,33.02 212.09,33.02 211.46,33.66 202.56,33.66 201.93,33.02 199.39,33.02 198.75,33.66 198.12,33.66 v195.58,31.12
  Route3 0.254: v360.68,88.9 360.68,86.36 E12.U2 | v376.56,90.8 377.82,89.53 377.82,79.38 379.1,78.1 379.1,68.58 377.82,67.31 377.82,62.23 376.56,60.96 v376.56,59.05 | v360.68,44.45 358.77,42.55 358.77,37.46 v356.87,35.56
  Bottom 0.254: F39.S2 17.78,21.59 18.41,20.95 22.86,20.95 23.5,20.32 24.77,20.32 26.04,21.59 29.84,21.59 F38.S2 | v360.68,88.9 362.58,90.8 365.76,90.8 366.39,90.17 375.29,90.17 375.92,90.8 v376.56,90.8 | v376.56,59.05 378.46,57.15 v379.73,57.15 | v114.3,12.06 108.58,17.78 97.79,17.78 97.16,17.14 89.53,17.14 88.9,17.78 85.09,17.78 81.28,13.97 72.39,13.97 68.58,17.78 59.69,17.78 55.88,13.97 46.99,13.97 45.72,15.24 43.18,15.24 F37.U2
-OP1  (via drill 0.61)
  Top 0.254: v295.91,39.37 298.45,36.83 298.45,24.13 v303.53,19.05
  Route2 0.254: v363.22,117.47 365.76,120.02 368.3,120.02 369.57,118.74 376.56,118.74 377.82,120.02 382.27,120.02 E10.F2
  Route3 0.254: v339.09,113.03 339.73,112.39 339.73,77.47 330.2,67.94 v330.2,55.88 | v319.4,53.34 317.5,51.44 317.5,24.77 v318.77,23.49
  Bottom 0.254: v295.91,39.37 290.19,39.37 289.56,40.01 285.12,40.01 284.48,40.64 F18.K2 | v303.53,19.05 306.07,19.05 F16.T2 306.7,19.69 307.34,19.69 307.34,22.23 308.61,23.49 313.06,23.49 313.69,24.13 318.13,24.13 v318.77,23.49 | v363.22,117.47 361.31,115.57 351.79,115.57 351.15,116.2 348.62,116.2 345.44,113.03 v339.09,113.03 | v330.2,55.88 327.02,55.88 323.85,52.7 320.04,52.7 v319.4,53.34
-OP2  (via drill 0.61)
  Top 0.254: B21.T2 243.21,292.74 244.47,294 244.47,315.6 243.21,316.87 B21.J2 | v287.02,28.58 286.38,29.21 286.38,30.48 285.75,31.12 285.75,73.66 | 285.75,73.66 v287.02,74.93 | v399.42,77.47 400.05,78.1 400.05,102.87 398.78,104.14 E09.M2 398.14,105.41 396.88,106.68 v396.88,115.57 | v280.67,165.1 280.04,164.47 280.04,163.19 279.4,162.56 v279.4,149.22 | v279.4,82.55 279.4,81.91 281.31,80.01 281.31,78.1 285.75,73.66
  Route2 0.254: v287.02,28.58 284.48,28.58 F18.P2 | v269.88,175.89 v280.67,165.1
  Route3 0.254: v246.38,187.32 247.65,188.59 247.65,208.28 244.47,211.45 244.47,290.2 243.21,291.47 B21.T2 | v279.4,149.22 279.4,139.06 280.67,137.79 280.67,135.89 279.4,134.62 279.4,119.38 282.57,116.2 282.57,99.06 279.4,95.88 v279.4,82.55
  Bottom 0.254: v287.02,74.93 300.99,74.93 302.89,73.02 304.8,73.02 305.44,72.39 334.64,72.39 337.82,75.56 343.54,75.56 344.17,74.93 348.62,74.93 349.25,74.29 372.11,74.29 374.65,76.83 381.63,76.83 382.9,78.1 398.78,78.1 v399.42,77.47 | v396.88,115.57 391.8,115.57 391.16,116.2 388.62,116.2 387.99,115.57 379.1,115.57 378.46,116.2 370.2,116.2 370.2,120.02 E11.F2 | v246.38,187.32 251.46,182.25 252.73,182.25 254,180.97 254,178.44 255.91,178.44 257.81,176.53 264.16,176.53 264.8,175.89 v269.88,175.89
-OPR  (via drill 0.61)
  Top 0.254: v394.97,123.82 396.88,125.73 v396.88,143.51 v396.88,149.86 | v417.19,149.22 419.1,151.13 419.1,160.02 420.37,161.29 D07.R2 | v265.43,43.82 263.52,45.72 263.52,66.67 260.35,69.85 v260.35,83.18 | v261.62,116.2 263.52,118.11 v263.52,143.51 | v294,143.51 294,148.59 D17.V2
  Route3 0.254: v260.35,83.18 260.35,114.93 v261.62,116.2
  Bottom 0.254: v394.97,123.82 393.06,125.73 391.8,125.73 391.16,125.09 383.54,125.09 377.19,118.74 374.01,118.74 373.38,118.11 E11.H2 | v396.88,143.51 397.51,144.14 411.48,144.14 416.56,149.22 v417.19,149.22 | v265.43,43.82 267.33,41.91 271.14,41.91 F19.K2 | v263.52,143.51 264.16,142.88 293.37,142.88 v294,143.51 | v396.88,149.86 396.24,150.5 393.7,150.5 392.43,149.22 391.16,149.22 389.25,151.13 380.37,151.13 379.73,150.5 377.19,150.5 376.56,151.13 367.67,151.13 367.03,150.5 364.49,150.5 363.86,151.13 356.24,151.13 354.33,149.22 353.06,149.22 351.15,151.13 342.26,151.13 341.63,150.5 339.09,150.5 338.45,151.13 329.56,151.13 328.93,150.5 326.39,150.5 325.75,151.13 323.21,151.13 319.4,147.32 310.51,147.32 307.34,150.5 300.99,150.5 300.36,151.13 295.27,151.13 294,149.86 D17.V2
-PBB  (via drill 0.61)
  Route2 0.254: v215.9,120.02 219.71,116.2 224.79,116.2 228.6,112.39 238.76,112.39 239.4,113.03 241.3,113.03 264.16,90.17 269.24,90.17 278.13,81.28 278.13,76.2 288.29,76.2 292.74,71.75 347.98,71.75 349.88,73.66 372.75,73.66 374.65,71.75 382.9,71.75 384.18,73.02 389.89,73.02 391.16,71.75 v392.43,71.75
  Route3 0.254: v392.43,71.75 392.43,71.12 384.18,62.87 384.18,52.7 382.9,51.44 F10.F2 | v413.38,71.75 414.02,72.39 414.02,80.64 412.75,81.91 412.75,83.82 422.27,93.34 422.27,113.66 425.45,116.84 425.45,147.32 424.18,148.59 424.18,151.76 D07.U2 | v215.9,120.02 215.9,130.81 212.72,133.99 212.72,136.53 209.55,139.7 209.55,200.66 210.19,201.29 210.19,204.47 209.55,205.1 209.55,220.34 208.28,221.61 C24.U2
  Bottom 0.254: v413.38,71.75 v392.43,71.75
-PBSH  (via drill 0.61)
  Top 0.254: v381,142.24 381,181.61 382.27,182.88 382.27,186.69 D10.F2 | v412.75,77.47 v412.75,142.88 | v442.6,76.2 444.5,74.29 444.5,33.66 445.77,32.38 F05.N2 446.4,31.12 446.4,30.48 447.68,29.21 447.68,17.78 448.94,16.51 F05.U2
  Bottom 0.254: v381,142.24 381.63,141.6 398.78,141.6 400.05,142.88 v412.75,142.88 | v412.75,77.47 413.38,76.83 431.17,76.83 431.8,76.2 v442.6,76.2
-PE  (via drill 0.61)
  Top 0.254: 434.98,78.74 434.98,86.99 436.25,88.27 436.25,91.44 E06.S2 | 434.98,78.74 434.98,27.3 433.7,26.03 F06.R2 | v436.88,78.74 434.98,78.74
  Bottom 0.254: v436.88,78.74 474.35,78.74 474.35,85.09 E03.U2
-PE_SEL  (via drill 0.61)
  Top 0.254: v428.62,139.06 v428.62,100.33 | v374.65,347.35 v374.65,139.7 | v209.55,347.98 209.55,369.57 208.28,370.84 A24.P2
  Route2 0.254: v140.97,364.49 139.7,364.49 138.43,363.22 137.79,363.22 137.16,363.86 128.27,363.86 124.46,360.05 115.57,360.05 109.22,366.4 102.87,366.4 99.06,370.21 92.71,370.21 83.82,379.1 77.47,379.1 73.66,382.91 64.77,382.91 60.96,379.1 50.8,379.1 44.45,385.45 39.37,385.45 35.56,389.25 31.11,389.25 30.48,389.89 A38.H2 | v167,363.86 175.26,363.86 175.9,363.22 184.78,363.22 188.59,367.03 194.94,367.03 198.12,370.21 200.66,370.21 201.29,369.57 206.38,369.57 207.65,370.84 A24.P2
  Bottom 0.254: A38.J2 27.3,387.99 29.21,389.89 29.84,389.89 A38.H2 | v428.62,100.33 434.98,100.33 436.25,99.06 E06.P2 | v428.62,139.06 410.21,139.06 409.57,138.43 407.67,138.43 407.04,139.06 402.59,139.06 401.95,138.43 394.97,138.43 393.7,139.7 v374.65,139.7 | v374.65,347.35 327.02,347.35 326.39,346.71 285.12,346.71 283.85,345.44 264.16,345.44 263.52,344.81 251.46,344.81 248.92,347.35 235.59,347.35 234.95,346.71 225.43,346.71 224.16,347.98 v209.55,347.98 | v140.97,364.49 141.6,363.86 147.96,363.86 151.76,360.05 162.56,360.05 166.37,363.86 v167,363.86
-PE_SET  (via drill 0.61)
  Top 0.254: v397.51,151.13 395.61,153.03 395.61,154.94 D09.T2
  Route3 0.254: v425.45,148.59 426.08,147.95 426.08,140.34 428.62,137.79 428.62,104.14 434.98,97.79 434.98,87.63 436.25,86.36 E06.U2
  Bottom 0.254: v425.45,148.59 423.55,150.5 415.29,150.5 414.65,151.13 405.76,151.13 405.13,150.5 402.59,150.5 401.95,151.13 v397.51,151.13
-PGZ  (via drill 0.61)
  Route3 0.254: v360.68,120.65 360.68,118.11 E12.H2 | v372.75,121.28 374.65,123.19 374.65,137.16 377.82,140.34 377.82,150.5 v373.38,154.94 | v369.57,158.75 368.3,160.02 368.3,180.34 365.12,183.51 365.12,215.26 361.95,218.44 361.95,221.61 371.48,231.14 371.48,239.39 370.2,240.66 370.2,243.84 C11.L2
  Bottom 0.254: v360.68,120.65 362.58,122.55 365.76,122.55 366.39,121.92 372.11,121.92 v372.75,121.28 | v373.38,154.94 v369.57,158.75
-PIR  (via drill 0.61)
  Top 0.254: v242.57,203.84 243.84,205.1 243.84,215.9 v241.94,217.81
  Route2 0.254: v190.5,54.61 192.41,52.7 198.75,52.7 201.93,49.53 208.28,49.53 212.09,45.72 219.07,45.72 220.34,46.99 F23.H2 | v182.88,193.04 185.42,195.58 187.96,195.58 188.59,194.94 197.49,194.94 198.12,195.58 200.66,195.58 201.29,194.94 208.28,194.94 212.09,198.75 215.26,198.75 215.9,198.12 226.06,198.12 226.69,198.75 235.59,198.75 236.22,198.12 236.85,198.12 v242.57,203.84 | v241.94,217.81 242.57,217.17 281.94,217.17 298.45,233.68 302.26,233.68 306.07,229.87 313.69,229.87 v315.6,231.78
  Route3 0.254: v190.5,54.61 184.15,60.96 184.15,75.56 180.97,78.74 180.97,191.13 v182.88,193.04 | v328.3,236.85 327.02,238.12 327.02,252.73 325.75,254 325.75,255.27 327.02,256.54 327.02,273.05 321.94,278.13 321.94,285.12 319.4,287.66 319.4,290.2 320.68,291.47 320.68,293.37 320.04,294 320.04,297.18 319.4,297.81 B15.R2
  Bottom 0.254: v315.6,231.78 316.23,231.14 317.5,231.14 318.13,230.5 321.94,230.5 v328.3,236.85
-PISEL  (via drill 0.61)
  Top 0.254: D38.V2 27.3,149.86 27.94,150.5 27.94,154.31 28.57,154.94 28.57,160.02 29.84,161.29 29.84,164.47 D38.P2 30.48,165.73 31.75,167 31.75,188.59 30.48,189.86 D38.E2 | v12.7,53.34 12.7,142.24 17.78,147.32 v17.78,150.5
  Bottom 0.254: F40.J2 1.91,45.09 3.81,46.99 4.45,46.99 F40.H2 5.08,48.26 5.71,48.9 8.26,48.9 v12.7,53.34 | v17.78,150.5 18.41,151.13 22.86,151.13 24.13,149.86 26.67,149.86 D38.V2
-PPC  (via drill 0.61)
  Top 0.254: A33.T2 90.17,362.59 90.17,367.67 A33.R2 90.17,368.94 90.17,374.02 A33.N2 90.17,375.29 90.17,380.37 A33.L2 90.17,381.64 90.17,386.72 A33.J2 90.17,387.99 90.17,393.06 A33.F2 90.17,394.34 90.17,399.42 A33.D2 | v2.54,274.32 3.17,273.69 3.17,246.38 1.91,245.11 C40.L2 | v57.78,275.59 60.33,278.13 v60.33,295.28 | 66.67,321.95 65.41,323.22 B35.F2 | 66.67,321.95 66.67,300.36 65.41,299.09 B35.R2 | 66.67,321.95 v66.67,360.68 66.67,375.29 66.04,375.92 66.04,379.73 65.41,380.37 A35.L2 | v414.02,240.66 412.75,239.39 412.75,236.85 411.48,235.59 C08.P2 | v263.52,243.84 v263.52,310.52 | v358.77,349.25 358.77,375.92 360.05,377.19 A12.M2 | v269.88,347.98 269.88,313.06 268.61,311.79 B19.L2
  Route2 0.254: C08.T2 408.31,226.06 408.31,230.5 408.94,230.5 410.85,232.41 410.85,234.31 C08.P2 | v179.71,349.25 180.97,347.98 183.51,347.98 184.15,348.62 206.38,348.62 208.28,346.71 v255.27,346.71
  Route3 0.254: v87.63,351.16 88.9,352.43 88.9,360.05 90.17,361.31 A33.T2
  Bottom 0.254: A37.T2 40.01,361.31 41.27,360.05 48.26,360.05 48.9,360.68 57.78,360.68 58.42,360.05 60.96,360.05 61.59,360.68 v66.67,360.68 70.48,360.68 74.3,356.87 81.92,356.87 86.36,361.31 90.17,361.31 A33.T2 | A29.R2 140.97,368.3 137.16,368.3 135.25,370.21 126.36,370.21 125.73,369.57 124.46,369.57 123.19,370.84 120.65,370.84 119.38,369.57 111.76,369.57 110.49,370.84 107.95,370.84 106.68,369.57 97.79,369.57 97.16,370.21 92.08,370.21 90.81,368.94 A33.R2 | v2.54,274.32 4.45,276.23 14.61,276.23 15.24,275.59 v57.78,275.59 | v60.33,295.28 60.33,298.45 64.77,298.45 B35.R2 | v414.02,240.66 412.75,239.39 402.59,239.39 401.95,240.03 394.33,240.03 393.7,239.39 389.89,239.39 389.25,240.03 380.37,240.03 379.73,239.39 377.19,239.39 376.56,240.03 367.67,240.03 363.86,236.22 356.87,236.22 353.06,240.03 344.81,240.03 344.17,239.39 339.09,239.39 338.45,240.03 329.56,240.03 328.93,239.39 326.39,239.39 325.12,240.66 322.58,240.66 C15.M2 321.94,241.3 318.13,241.3 316.23,239.39 313.69,239.39 312.42,240.66 309.88,240.66 C16.M2 309.25,240.66 307.98,239.39 300.99,239.39 299.72,240.66 297.18,240.66 C17.M2 296.55,241.94 292.74,241.94 291.46,243.2 290.19,243.2 288.93,241.94 284.48,241.94 C18.M2 283.85,241.3 280.04,241.3 278.13,239.39 275.59,239.39 274.32,240.66 271.78,240.66 C19.M2 271.14,240.66 269.88,239.39 264.8,239.39 264.16,240.03 263.52,240.03 | 263.52,240.03 259.71,240.03 259.08,240.66 C20.M2 | v263.52,310.52 267.97,310.52 B19.L2 | 263.52,240.03 v263.52,243.84 | v358.77,349.25 358.14,348.62 325.75,348.62 325.12,347.98 v269.88,347.98 267.97,349.89 258.44,349.89 v255.27,346.71
  Bottom 0.254: v87.63,351.16 90.81,347.98 158.75,347.98 159.38,347.35 160.66,347.35 162.56,349.25 v179.71,349.25
-PT
  Route3 0.254: E06.H2 436.25,118.11 431.8,118.11 431.8,151.13 433.07,152.4 433.07,153.67 428.62,158.11 428.62,165.73 433.07,170.18 433.07,173.99 D06.L2
-R1MB  (via drill 0.61)
  Top 0.254: v314.32,206.38 314.32,270.51 307.98,276.86 307.98,295.91 308.61,296.55 308.61,300.36 309.25,300.99 B16.P2 | v381,206.38 381,183.51 v379.1,181.61 | v444.5,94.61 444.5,88.27 450.85,81.91 450.85,55.88 449.58,54.61 F05.E2
  Route2 0.254: v379.1,181.61 376.56,179.07 370.2,179.07 370.2,175.26 D11.L2
  Route3 0.254: F05.L2 446.4,38.73 447.68,40.01 447.68,52.07 448.94,53.34 F05.E2 | v444.5,94.61 444.5,148.59 441.32,151.76 441.32,181.61 v440.06,182.88
  Bottom 0.254: v379.1,181.61 382.9,185.42 391.16,185.42 391.8,186.06 400.69,186.06 401.32,185.42 403.86,185.42 404.5,186.06 410.21,186.06 410.85,185.42 416.56,185.42 417.19,186.06 423.55,186.06 424.18,185.42 425.45,185.42 | 425.45,185.42 429.26,185.42 430.53,186.69 433.07,186.69 D06.F2 | v314.32,206.38 336.55,206.38 337.19,205.74 380.37,205.74 v381,206.38 | v440.06,182.88 437.51,182.88 434.34,179.7 427.99,179.7 427.36,179.07 426.72,179.07 425.45,180.34 425.45,185.42
-READ  (via drill 0.61)
  Top 0.254: v167.64,87.63 168.28,88.27 168.28,163.19 169.54,164.47 D27.P2
  Route2 0.254: v96.52,84.45 92.71,84.45 86.36,90.8 80.01,90.8 73.66,97.16 67.31,97.16 60.96,103.5 53.98,103.5 52.7,102.23 E36.N2
  Bottom 0.254: v96.52,84.45 99.06,84.45 103.5,80.01 160.02,80.01 v167.64,87.63
-RIMA  (via drill 0.61)
  Top 0.254: E13.F2 344.81,120.02 345.44,119.38 345.44,115.57 346.71,114.3 346.71,112.39 347.35,111.76 E13.K2 | v285.75,138.43 285.75,375.92 284.48,377.19 A18.M2 | v317.5,138.43 v317.5,123.82
  Route3 0.254: 333.38,90.17 333.38,84.45 332.11,83.18 E14.V2 | 333.38,90.17 334.64,91.44 E14.S2 | 333.38,90.17 333.38,99.69 332.11,100.96 E14.N2 332.11,102.23 333.38,103.5 333.38,109.22 334.64,110.49 E14.K2
  Bottom 0.254: E14.K2 335.28,110.49 339.73,110.49 341,109.22 342.26,109.22 343.54,110.49 347.35,110.49 E13.K2 | v285.75,138.43 292.1,138.43 292.74,137.79 302.26,137.79 302.89,138.43 304.8,138.43 305.44,137.79 314.96,137.79 315.6,138.43 v317.5,138.43 | v317.5,123.82 321.94,123.82 E15.E2 322.58,123.19 325.12,123.19 327.02,121.28 331.47,121.28 E14.F2 332.11,120.02 333.38,118.74 338.45,118.74 339.09,119.38 343.54,119.38 344.17,120.02 E13.F2
-RIPC  (via drill 0.61)
  Top 0.254: C14.N2 331.47,238.76 330.2,240.03 330.2,252.09 331.47,253.36 331.47,256.54 C14.F2 | v327.02,204.47 v327.02,226.06 | v334.64,231.78 334.64,229.23 C14.S2
  Route3 0.254: C14.K2 334.64,247.01 333.38,245.75 333.38,240.03 332.11,238.76 C14.N2 | v288.29,184.78 292.1,188.59 292.1,201.93 v294,203.84
  Bottom 0.254: C15.E2 322.58,259.72 323.21,259.08 327.66,259.08 328.93,257.81 331.47,257.81 C14.F2 | v288.29,184.78 284.48,184.78 D18.H2 | v294,203.84 295.27,205.1 308.61,205.1 309.25,204.47 314.96,204.47 315.6,205.1 326.39,205.1 v327.02,204.47 | v327.02,226.06 327.66,226.69 333.38,226.69 334.64,227.97 C14.S2 | v334.64,231.78 333.38,233.04 332.11,233.04 332.11,237.49 C14.N2
-ROTL  (via drill 0.61)
  Top 0.254: F17.S2 296.55,22.86 296.55,27.94 F17.P2 | v245.75,310.52 247.65,308.61 v247.65,73.02 | v288.93,73.02 v288.93,32.38
  Route2 0.254: v245.75,310.52 243.21,310.52 B21.L2
  Bottom 0.254: v247.65,73.02 248.28,72.39 288.29,72.39 v288.93,73.02 | v288.93,32.38 293.37,32.38 F17.N2 294,31.12 294.64,31.12 296.55,29.21 F17.P2
-ROTR  (via drill 0.61)
  Top 0.254: F17.J2 294,43.82 294.64,43.18 294.64,39.37 295.27,38.73 295.27,27.3 294,26.03 F17.R2 | v296.55,44.45 296.55,46.99 F17.H2 | v149.22,314.33 149.22,285.12 147.32,283.21 147.32,271.78 v142.88,267.34 | v138.43,219.07 136.53,217.17 136.53,197.48 v134.62,195.58
  Route2 0.254: v219.07,370.84 217.81,369.57 214.63,369.57 211.46,366.4 202.56,366.4 201.93,367.03 200.03,367.03 193.68,360.68 186.69,360.68 186.06,360.05 177.16,360.05 176.53,360.68 174.62,360.68 164.47,350.52 153.03,350.52 v151.76,349.25 | v144.15,107.31 167,84.45 175.26,84.45 175.9,83.82 182.25,83.82 185.42,80.64 203.2,80.64 207.01,76.83 214.63,76.83 216.53,74.93 241.94,74.93 257.81,59.05 262.89,59.05 266.7,55.25 276.86,55.25 277.5,55.88 285.12,55.88 292.74,48.26 296.55,48.26 F17.H2
  Route3 0.254: v151.76,349.25 149.22,346.71 v149.22,314.33 | v142.88,267.34 142.88,223.52 v138.43,219.07 | v134.62,195.58 133.35,194.31 133.35,175.26 132.08,173.99 132.08,173.35 133.35,172.09 133.35,124.46 139.7,118.11 139.7,111.76 v144.15,107.31
  Bottom 0.254: F19.S2 271.78,22.86 272.42,23.49 276.86,23.49 277.5,24.13 278.76,24.13 279.4,23.49 288.29,23.49 289.56,24.77 293.37,24.77 F17.R2 | v296.55,44.45 294,44.45 F17.J2 | v219.07,370.84 219.71,370.21 221.62,370.21 225.43,374.02 229.87,374.02 A22.N2
-RSF  (via drill 0.61)
  Top 0.254: v198.12,403.23 200.03,401.32 210.19,401.32 220.98,412.12 244.47,412.12 244.47,408.31 247.65,405.13 v247.65,374.02
  Route3 0.254: v198.12,403.23 197.49,403.86 197.49,405.13 188.59,405.13 187.96,404.5 180.97,404.5 155.57,379.1 155.57,367.67 142.88,354.97 142.88,310.52 130.18,297.81 130.18,154.94 127,151.76 127,97.79 123.83,94.61 123.83,48.26 119.38,48.26 F31.H2 | v247.65,374.02 255.91,365.76 v255.91,363.86
  Bottom 0.254: v255.91,363.86 264.16,363.86 265.43,362.59 267.97,362.59 A19.T2
-RUN  (via drill 0.61)
  Top 0.254: A35.S2 67.94,365.76 67.94,370.84 A35.P2 67.94,372.11 67.94,375.29 66.67,376.56 66.67,382.27 67.94,383.54 A35.K2 | v75.56,40.01 82.55,46.99 82.55,292.1 81.28,293.37 81.28,294.64 B34.S2 | v65.41,364.49 63.5,362.59 63.5,331.47 57.15,325.12 57.15,303.53 55.88,302.26 B36.P2
  Route2 0.254: v65.41,364.49 67.94,364.49 A35.S2
  Bottom 0.254: v75.56,40.01 62.23,26.67 61.59,26.67 60.96,27.3 53.98,27.3 52.7,26.03 F36.R2 | B21.S2 245.75,295.91 244.47,297.18 237.49,297.18 236.85,296.55 227.97,296.55 227.33,297.18 224.79,297.18 224.16,296.55 215.26,296.55 214.63,297.18 212.09,297.18 211.46,296.55 202.56,296.55 201.93,297.18 199.39,297.18 198.75,296.55 189.87,296.55 189.23,297.18 186.69,297.18 186.06,296.55 177.16,296.55 176.53,297.18 173.99,297.18 173.35,296.55 164.47,296.55 163.83,297.18 161.29,297.18 160.66,296.55 151.76,296.55 151.13,297.18 148.59,297.18 147.96,296.55 139.06,296.55 138.43,297.18 135.89,297.18 135.25,296.55 126.36,296.55 125.73,297.18 123.19,297.18 121.92,295.91 119.38,295.91 B31.S2 118.75,295.91 117.47,297.18 110.49,297.18 109.86,296.55 100.97,296.55 100.33,297.18 97.79,297.18 97.16,296.55 88.27,296.55 87.63,297.18 85.09,297.18 83.82,295.91 81.28,295.91 B34.S2 80.64,295.91 78.11,295.91 73.66,300.36 71.12,300.36 70.48,299.72 61.59,299.72 60.96,300.36 56.52,300.36 55.88,300.99 B36.P2
-S  (via drill 0.61)
  Top 0.254: A23.J2 217.81,386.72 217.81,386.08 219.07,384.81 219.07,376.56 217.81,375.29 A23.N2 217.81,374.02 217.81,370.21 219.07,368.94 219.07,363.86 220.34,362.59 220.34,359.41 A23.U2 220.34,358.14 220.34,343.54 v219.71,342.9 | v295.27,393.7 295.27,386.08 296.55,384.81 A17.K2 | B40.F2 1.27,323.22 1.27,318.14 B40.J2 | v156.84,311.79 158.75,313.69 v158.75,342.9 | v18.41,325.75 19.05,326.39 v19.05,349.89 | v139.06,352.43 141.6,349.89 v141.6,342.9
  Route2 0.254: A23.H2 220.34,389.89 218.44,387.99 217.81,387.99 A23.J2 | v156.84,311.79 154.31,311.79 B28.L2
